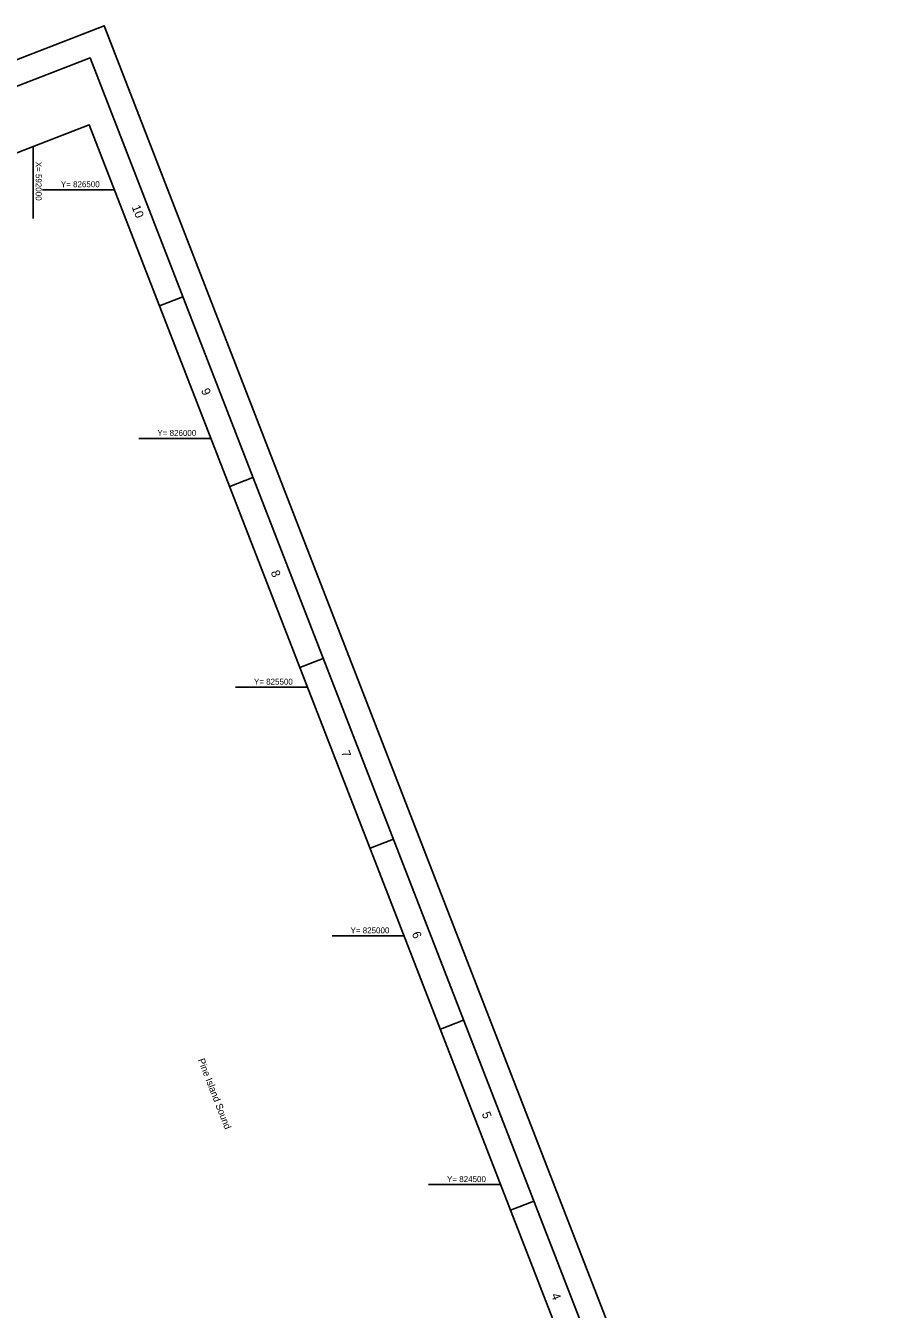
# Model space of a CAD drawing. Extents: x 588973 to 593734, y 821498 to 826830.
# Drawn here: x 591985 to 593734, y 824249 to 826830 of the extents above; entities that cross this region are included whole.
import ezdxf

# ---------------------------------------------------------------- set-up
doc = ezdxf.new("R2010")
doc.units = 0
for name, color, linetype in [('G-ANNO-NPLT', 7, 'Continuous'), ('G-ANNO-TTLB', 7, 'Continuous'), ('V-SITE-WATR', 7, 'Continuous'), ('V-TOPO-COOR-STAT', 7, 'Continuous')]:
    doc.layers.add(name, color=color, linetype=linetype)

msp = doc.modelspace()

# ---------------------------------------------------------------- linework, layer by layer
at = {"layer": 'G-ANNO-NPLT'}
msp.add_lwpolyline([(592142.7, 826829.7), (593734.3, 822727.7), (590564.5, 821497.8), (588973, 825599.9)], close=True, dxfattribs=at)
msp.add_lwpolyline([(592096.1, 826811.6), (592142.7, 826829.7), (592160.8, 826783.1)], dxfattribs=at)
at = {"layer": 'G-ANNO-TTLB'}
for p, q in [((592300.5, 826284.9), (592253.9, 826266.8)), ((592441.6, 825921.3), (592395, 825903.2)), ((592441.6, 825921.3), (592395, 825903.2)), ((592582.6, 825557.7), (592536, 825539.6)), ((592723.7, 825194.1), (592677.1, 825176)), ((592864.8, 824830.5), (592818.2, 824812.4)), ((593005.8, 824466.9), (592959.2, 824448.8))]:
    msp.add_line(p, q, dxfattribs=at)
for points in [[(589037.7, 825571.4), (590593, 821562.5), (593669.6, 822756.2), (592114.2, 826765)], [(593604.9, 822784.7), (592112.8, 826630.4), (589129.5, 825472.9), (590621.6, 821627.2)]]:
    msp.add_lwpolyline(points, close=True, dxfattribs=at)
at = {"layer": 'V-TOPO-COOR-STAT'}
for p, q in [((592000, 826441.8), (592000, 826586.6)), ((592018.6, 826500), (592163.4, 826500)), ((592212.6, 826000), (592357.4, 826000)), ((592406.6, 825500), (592551.4, 825500)), ((592600.6, 825000), (592745.4, 825000)), ((592794.6, 824500), (592939.4, 824500))]:
    msp.add_line(p, q, dxfattribs=at)

# ---------------------------------------------------------------- texts
at = {"layer": 'G-ANNO-TTLB'}
for s, p in [('10', (592197.7, 826465.4)), ('9', (592336.9, 826096.9)), ('8', (592477, 825731.1)), ('7', (592618.3, 825369)), ('6', (592760.4, 825004.8)), ('5', (592900.9, 824642.6)), ('4', (593040.4, 824278))]:
    msp.add_text(s, height=17.5, rotation=291.2052, dxfattribs=at).set_placement(p)
at = {"layer": 'V-SITE-WATR'}
msp.add_text('Pine Island Sound', height=13.92, rotation=291.2052, dxfattribs=at).set_placement((592330.8, 824750.6))
at = {"layer": 'V-TOPO-COOR-STAT'}
msp.add_text('X= 592000', height=12, rotation=270, dxfattribs=at).set_placement((592005, 826556.1))
for s, p in [('Y= 826500', (592055.6, 826505)), ('Y= 826000', (592249.6, 826005)), ('Y= 825500', (592443.6, 825505)), ('Y= 825000', (592637.6, 825005)), ('Y= 824500', (592831.6, 824505))]:
    msp.add_text(s, height=12, dxfattribs=at).set_placement(p)

doc.saveas('drawing.dxf')
